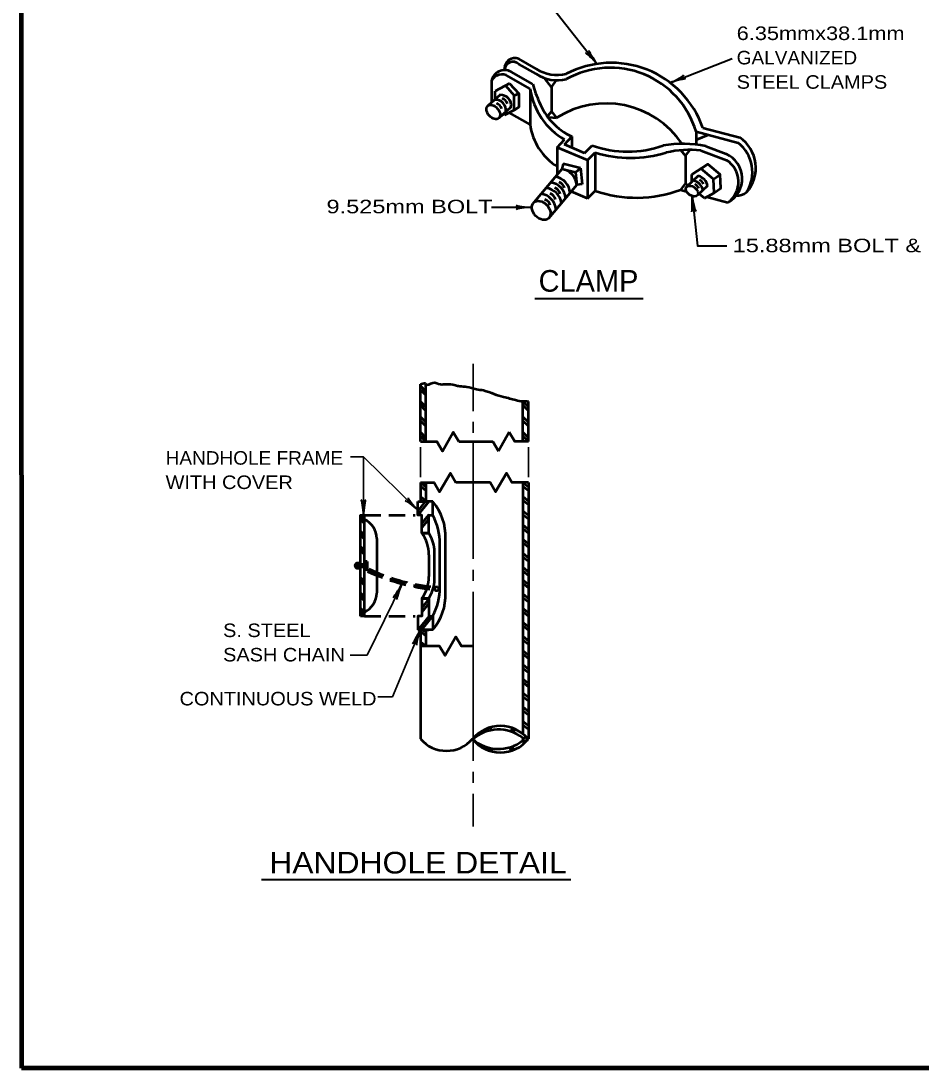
# Model space of a CAD drawing. Extents: x -23 to 690, y -228 to 443.
# Drawn here: x 24.3 to 190.5, y -0.6 to 192.8 of the extents above; entities that cross this region are included whole.
import ezdxf

# ---------------------------------------------------------------- set-up
doc = ezdxf.new("R2010")
doc.units = 0
doc.linetypes.add('MEDIUM_DASHED', pattern=[4.5, 3, -1.5])
doc.layers.add('1', color=7, linetype='Continuous', lineweight=35)

msp = doc.modelspace()

# ---------------------------------------------------------------- hatches: boundary and pattern name
at = {"layer": '1'}
msp.add_hatch(color=256, dxfattribs=at).paths.add_polyline_path([(87.083, 92.208, 1), (85.994, 92.208, 1)])

# ---------------------------------------------------------------- linework, layer by layer
at = {"layer": '1', "lineweight": 40}
for p, q in [((120.107, 198.311), (130.625, 184.906)), ((144.15, 181.442), (155.602, 185.881)), ((118.629, 158.401), (111.193, 158.401)), ((119.153, 141.59), (139.165, 141.59)), ((68.685, 34.21), (125.825, 34.21))]:
    msp.add_line(p, q, dxfattribs=at)
at = {"layer": '1', "lineweight": 53}
for p, q in [((119.441, 184.018), (116.221, 185.858)), ((119.441, 183.058), (116.221, 184.878)), ((118.301, 180.298), (114.281, 182.598)), ((118.801, 181.178), (114.781, 183.458)), ((122.241, 180.638), (120.961, 182.278)), ((122.241, 180.638), (123.201, 181.878)), ((111.181, 181.778), (111.181, 177.758)), ((114.521, 181.298), (111.841, 179.878)), ((113.761, 180.898), (115.381, 179.098)), ((118.301, 180.298), (118.301, 173.738)), ((112.741, 179.178), (110.481, 177.138)), ((111.841, 178.378), (111.841, 179.878)), ((114.761, 176.918), (112.521, 174.898)), ((122.241, 176.098), (123.181, 174.918)), ((113.361, 175.678), (113.561, 175.438)), ((118.301, 173.738), (114.501, 175.898)), ((121.761, 175.098), (123.181, 174.918)), ((148.961, 172.418), (156.741, 170.318)), ((148.961, 172.418), (148.961, 169.998)), ((150.181, 173.118), (157.001, 171.298)), ((123.321, 169.458), (124.681, 170.958)), ((124.641, 169.998), (126.001, 171.498)), ((126.001, 171.498), (126.001, 169.418)), ((149.081, 170.958), (151.161, 171.818)), ((128.901, 167.098), (123.321, 169.458)), ((123.321, 169.458), (123.321, 164.478)), ((128.361, 168.418), (124.641, 169.998)), ((128.361, 168.418), (129.781, 169.838)), ((128.901, 167.098), (130.321, 168.518)), ((130.321, 168.518), (130.321, 161.458)), ((147.001, 167.898), (146.161, 168.958)), ((147.001, 167.898), (147.881, 169.038)), ((149.841, 168.938), (154.561, 167.138)), ((150.721, 169.718), (154.501, 168.278)), ((124.401, 166.458), (124.161, 165.478)), ((127.581, 165.678), (124.401, 166.458)), ((128.901, 167.098), (128.901, 160.038)), ((147.001, 167.898), (147.001, 162.858)), ((124.161, 165.478), (118.981, 159.298)), ((126.661, 164.858), (124.161, 165.478)), ((127.581, 165.678), (126.661, 164.858)), ((126.661, 164.858), (126.921, 162.558)), ((127.581, 165.678), (127.921, 162.678)), ((148.181, 163.118), (148.141, 164.478)), ((152.181, 163.598), (149.861, 165.538)), ((126.921, 162.558), (121.721, 156.378)), ((127.921, 162.678), (126.921, 162.558)), ((147.001, 162.858), (146.061, 161.658)), ((147.001, 162.858), (147.381, 162.358)), ((149.361, 164.218), (147.141, 162.158)), ((128.901, 160.038), (125.881, 161.318)), ((128.901, 160.038), (130.321, 161.458)), ((146.061, 161.658), (147.161, 161.358)), ((151.081, 162.378), (149.241, 160.658)), ((150.481, 160.118), (149.521, 160.918)), ((150.941, 160.358), (154.821, 159.318)), ((98.073, 115.123), (98.073, 125.722)), ((99.073, 124.402), (98.073, 125.402)), ((99.073, 123.682), (98.073, 124.682)), ((99.073, 115.123), (99.073, 125.722)), ((99.073, 121.542), (98.073, 122.542)), ((116.973, 115.123), (116.973, 122.542)), ((117.973, 121.542), (116.973, 122.542)), ((117.973, 115.123), (117.973, 122.542)), ((99.073, 120.822), (98.073, 121.843)), ((117.973, 120.822), (116.973, 121.843)), ((99.073, 118.703), (98.073, 119.703)), ((99.073, 117.983), (98.073, 118.983)), ((117.973, 118.703), (116.973, 119.703)), ((117.973, 117.983), (116.973, 118.983)), ((99.073, 115.843), (98.073, 116.843)), ((99.073, 115.123), (98.073, 116.142)), ((114.453, 116.882), (112.433, 113.382)), ((117.973, 115.843), (116.973, 116.843)), ((117.973, 115.123), (116.973, 116.142)), ((105.133, 115.123), (111.433, 115.123)), ((112.433, 113.382), (111.433, 115.123)), ((98.073, 107.562), (98.073, 104.042)), ((98.073, 107.562), (99.073, 106.742)), ((98.073, 106.922), (99.073, 106.082)), ((99.073, 107.562), (99.073, 104.042)), ((116.973, 107.562), (117.973, 106.742)), ((116.973, 106.922), (117.973, 106.082)), ((117.973, 107.562), (117.973, 60.203)), ((98.073, 104.962), (99.073, 104.123)), ((116.973, 104.962), (117.973, 104.123)), ((97.573, 104.042), (99.573, 104.042)), ((99.573, 104.042), (97.573, 101.522)), ((98.933, 104.042), (97.573, 102.322)), ((98.073, 104.302), (98.393, 104.042)), ((100.333, 104.042), (98.313, 104.042)), ((116.973, 104.302), (117.973, 103.483)), ((87.733, 100.682), (86.973, 101.442)), ((87.733, 99.983), (86.973, 100.742)), ((87.733, 82.882), (87.733, 101.522)), ((99.573, 101.623), (98.313, 100.042)), ((99.573, 100.822), (98.313, 99.242)), ((116.973, 102.343), (117.973, 101.522)), ((116.973, 101.682), (117.973, 100.862)), ((116.973, 99.722), (117.973, 98.903)), ((116.973, 99.082), (117.973, 98.242)), ((87.733, 97.843), (86.973, 98.602)), ((87.733, 97.123), (86.973, 97.882)), ((90.013, 97.242), (90.013, 87.162)), ((99.573, 98.242), (98.313, 98.242)), ((102.653, 87.162), (102.653, 97.242)), ((116.973, 97.123), (117.973, 96.282)), ((87.733, 94.983), (86.973, 95.742)), ((87.733, 94.282), (86.973, 95.042)), ((100.633, 89.182), (100.633, 95.222)), ((101.653, 88.162), (101.653, 96.222)), ((116.973, 96.462), (117.973, 95.642)), ((88.233, 92.962), (87.733, 92.962)), ((87.853, 92.962), (87.853, 91.442)), ((87.933, 92.962), (87.933, 91.442)), ((87.933, 92.962), (87.933, 91.442)), ((88.013, 92.962), (88.013, 91.442)), ((88.013, 92.962), (88.013, 91.442)), ((88.073, 92.962), (88.073, 91.442)), ((88.133, 92.962), (88.133, 91.442)), ((88.153, 92.962), (88.153, 91.442)), ((88.193, 92.962), (88.193, 91.442)), ((88.233, 92.962), (88.233, 91.442)), ((99.633, 90.182), (99.633, 94.222)), ((116.973, 94.502), (117.973, 93.682)), ((116.973, 93.862), (117.973, 93.022)), ((87.733, 92.442), (86.973, 92.442)), ((87.733, 92.322), (86.973, 92.322)), ((87.733, 92.242), (86.973, 92.242)), ((87.733, 92.242), (86.973, 92.242)), ((87.733, 92.123), (86.973, 92.123)), ((87.733, 92.002), (86.973, 92.002)), ((87.733, 91.942), (86.973, 91.942)), ((88.233, 91.442), (87.733, 91.442)), ((116.973, 91.903), (117.973, 91.062)), ((116.973, 91.242), (117.973, 90.403)), ((87.733, 89.282), (86.973, 90.043)), ((87.733, 88.582), (86.973, 89.322)), ((116.973, 89.602), (117.973, 88.782)), ((87.733, 86.442), (86.973, 87.203)), ((116.973, 88.962), (117.973, 88.123)), ((87.733, 85.722), (86.973, 86.483)), ((99.573, 86.022), (98.313, 84.442)), ((99.573, 85.203), (98.313, 83.642)), ((116.973, 87.002), (117.973, 86.162)), ((116.973, 86.343), (117.973, 85.522)), ((87.733, 83.582), (86.973, 84.343)), ((87.733, 82.882), (86.973, 83.623)), ((116.973, 84.382), (117.973, 83.562)), ((116.973, 83.722), (117.973, 82.903)), ((87.733, 82.882), (86.973, 82.882)), ((99.653, 82.882), (97.633, 80.362)), ((100.333, 82.922), (98.273, 80.362)), ((116.973, 81.763), (117.973, 80.942)), ((97.573, 80.362), (99.573, 80.362)), ((98.073, 80.362), (98.073, 77.322)), ((98.073, 80.102), (99.073, 79.263)), ((100.333, 80.362), (98.313, 80.362)), ((98.553, 80.362), (99.073, 79.922)), ((99.073, 80.362), (99.073, 77.322)), ((116.973, 81.123), (117.973, 80.282)), ((98.073, 78.142), (99.053, 77.322)), ((98.073, 77.483), (98.253, 77.322)), ((116.973, 79.162), (117.973, 78.322)), ((116.973, 78.502), (117.973, 77.682)), ((116.973, 76.543), (117.973, 75.722)), ((116.973, 75.903), (117.973, 75.062)), ((116.973, 73.942), (117.973, 73.102)), ((116.973, 73.282), (117.973, 72.442)), ((116.973, 71.322), (117.973, 70.483)), ((116.973, 70.662), (117.973, 69.843)), ((116.973, 68.703), (117.973, 67.882)), ((116.973, 68.062), (117.973, 67.222)), ((116.973, 66.102), (117.973, 65.263)), ((116.973, 65.442), (117.973, 64.623)), ((110.433, 62.142), (110.633, 61.703)), ((110.913, 62.302), (111.133, 61.802)), ((115.013, 62.203), (114.713, 61.562)), ((115.473, 62.023), (115.193, 61.383)), ((116.973, 63.482), (117.973, 62.663)), ((116.973, 62.822), (117.973, 62.002)), ((116.673, 59.722), (117.853, 60.042)), ((116.973, 60.322), (117.613, 60.502)), ((110.613, 58.062), (110.833, 58.523)), ((111.093, 57.922), (111.333, 58.442)), ((114.833, 58.002), (114.533, 58.663)), ((115.313, 58.182), (115.013, 58.822))]:
    msp.add_line(p, q, dxfattribs=at)
at = {"layer": '1'}
for p, q in [((107.773, 120.763), (107.773, 129.502)), ((107.773, 118.763), (107.773, 116.742)), ((107.773, 115.123), (107.773, 111.362)), ((107.773, 114.722), (107.773, 93.462)), ((87.519, 112.294), (85.131, 112.307)), ((98.073, 108.582), (98.073, 114.123)), ((117.973, 108.582), (117.973, 114.123)), ((107.773, 91.442), (107.773, 89.422)), ((107.773, 87.403), (107.773, 56.122)), ((107.773, 54.102), (107.773, 52.082)), ((107.773, 50.082), (107.773, 44.042))]:
    msp.add_line(p, q, dxfattribs=at)
at = {"layer": '1', "linetype": 'MEDIUM_DASHED', "lineweight": 53}
for p, q in [((87.733, 101.522), (97.053, 101.522)), ((87.733, 82.882), (97.053, 82.882))]:
    msp.add_line(p, q, dxfattribs=at)
at = {"layer": '1', "lineweight": 158}
msp.add_line((684.026, -0.611), (24.36, -0.611), dxfattribs=at)
msp.add_lwpolyline([(684.026, 437.805), (24.276, 437.722), (24.36, -0.611)], dxfattribs=at)
at = {"layer": '1', "lineweight": 53}
for points in [[(114.521, 181.298), (116.201, 179.438), (116.201, 176.918), (115.381, 176.338), (113.561, 175.438)], [(122.241, 180.638), (122.241, 176.098), (121.601, 175.298)], [(115.381, 176.338), (115.381, 179.098), (116.201, 179.438)], [(150.481, 160.118), (152.261, 161.078), (153.501, 161.938), (153.421, 164.458), (151.101, 166.398), (148.141, 164.478)], [(152.261, 161.078), (152.181, 163.598), (153.421, 164.458)], [(98.073, 115.123), (101.093, 115.123), (102.093, 113.382), (104.113, 116.882), (105.133, 115.123)], [(117.973, 115.123), (115.453, 115.123), (114.453, 116.882)], [(98.073, 107.562), (100.593, 107.562), (101.593, 105.822), (103.613, 109.322), (104.613, 107.562)], [(117.973, 107.562), (114.953, 107.562), (113.953, 109.322), (111.933, 105.822), (110.913, 107.562), (104.613, 107.562)], [(116.973, 107.562), (116.973, 87.123), (116.973, 61.102)], [(98.313, 98.242), (98.313, 101.522), (97.573, 101.522), (97.573, 104.042)], [(98.313, 98.242), (99.573, 98.242), (99.573, 101.522), (100.333, 101.522), (100.333, 104.042)], [(86.973, 82.882), (86.973, 101.522), (87.733, 101.522)], [(99.573, 86.142), (98.313, 86.142), (98.313, 82.882), (97.573, 82.882), (97.573, 80.362)], [(98.313, 86.142), (99.573, 86.142), (99.573, 82.882), (100.333, 82.882), (100.333, 80.362)], [(107.653, 77.322), (105.633, 77.322), (104.613, 79.082), (102.613, 75.582), (101.593, 77.322), (98.073, 77.322), (98.073, 60.203)]]:
    msp.add_lwpolyline(points, dxfattribs=at)
at = {"layer": '1', "lineweight": 40}
msp.add_lwpolyline([(148.224, 160.489), (149.21, 151.327), (154.65, 151.327)], dxfattribs=at)
at = {"layer": '1'}
for points in [[(97.573, 102.459), (87.519, 112.294), (87.519, 101.522)], [(94.602, 88.752), (88.2, 75.673), (85.088, 75.679)], [(98.034, 80.345), (92.887, 67.957), (90.194, 67.957)]]:
    msp.add_lwpolyline(points, dxfattribs=at)
at = {"layer": '1', "lineweight": 53}
for centre, radius in [((86.538, 92.208), 0.545), ((101.059, 87.924), 0.378)]:
    msp.add_circle(centre, radius, dxfattribs=at)
for centre, radius, start, end in [((115.524, 184.021), 1.967, 68.98454, 184.96528), ((115.167, 183.674), 1.613, 48.79801, 173.73367), ((123.336, 189.995), 7.131, 236.83956, 283.32479), ((133.299, 167.215), 17.892, 19.29143, 117.70819), ((133.089, 167.641), 16.566, 16.7434, 119.30902), ((113.595, 181.305), 2.464, 61.16852, 169.07366), ((113.089, 180.813), 2.14, 56.06469, 153.37669), ((123.284, 188.727), 6.854, 235.84201, 284.32234), ((130.95, 182.087), 12.777, 188.06983, 240.59731), ((139.874, 186.899), 21.84, 195.21089, 204.37149), ((111.911, 176.397), 1.909, 349.61263, 94.38617), ((112.883, 177.267), 1.909, 349.61263, 94.38617), ((112.506, 176.938), 1.742, 20.88408, 69.09679), ((111.455, 176.011), 1.742, 20.88408, 69.09679), ((131.129, 182.346), 12.008, 201.80286, 244.70416), ((132.334, 160.727), 16.89, 33.86522, 122.8499), ((129.015, 175.115), 10.803, 187.30417, 238.23787), ((152.415, 164.901), 6.939, 327.83586, 51.43283), ((153.241, 165.692), 6.752, 318.38164, 56.15447), ((136.339, 188.098), 19.396, 250.25742, 289.74258), ((136.873, 190.32), 22.763, 253.27137, 286.72862), ((146.475, 148.391), 21.748, 78.72641, 99.48511), ((147.907, 149.265), 19.77, 84.35687, 103.10294), ((152.516, 163.715), 4.969, 297.71146, 66.56345), ((152.083, 163.134), 4.701, 305.70046, 58.26699), ((123.731, 162.304), 3.193, 4.65558, 82.27962), ((121.684, 159.86), 3.193, 4.74535, 82.35434), ((122.509, 160.869), 3.193, 4.32722, 81.54855), ((123.164, 161.617), 1.531, 14.18506, 70.66849), ((147.854, 161.069), 2.406, 11.41742, 74.57891), ((148.099, 161.38), 1.432, 21.50211, 64.13038), ((148.72, 161.894), 2.406, 11.41742, 74.57891), ((148.974, 162.181), 1.432, 21.50211, 64.13038), ((119.913, 157.722), 3.193, 5.19441, 82.73082), ((120.921, 158.791), 3.193, 7.29827, 83.92311), ((121.515, 159.509), 1.531, 14.18506, 70.66849), ((122.37, 160.548), 1.531, 14.18506, 70.66849), ((137.914, 183.47), 23.278, 250.96338, 290.4942), ((156.114, 164.254), 3.743, 273.11257, 305.52158), ((120.537, 158.409), 1.531, 14.18506, 70.66849), ((92.937, 97.724), 9.729, 357.13004, 40.48815), ((85.9, 97.092), 4.106, 2.02606, 63.44439), ((89.84, 96.116), 11.806, 0.54939, 27.24732), ((92.647, 94.174), 6.982, 0.31998, 35.66459), ((93.502, 94.423), 7.18, 6.38376, 32.16514), ((92.647, 90.22), 6.982, 324.33541, 359.68002), ((93.502, 89.972), 7.18, 327.83486, 353.61624), ((85.9, 87.302), 4.106, 296.55561, 357.97394), ((89.84, 88.314), 11.806, 332.75268, 359.45061), ((92.937, 86.705), 9.729, 319.51185, 2.86996), ((112.451, 54.751), 7.178, 51.54154, 132.04732), ((112.81, 56.013), 6.576, 38.8447, 141.1553), ((102.856, 64.313), 6.317, 220.71167, 319.28832), ((112.81, 64.262), 6.576, 218.22248, 321.77751), ((112.451, 65.523), 7.178, 227.95268, 308.4983), ((116.738, 60.139), 0.294, 307.8273, 52.77092)]:
    msp.add_arc(centre, radius, start, end, dxfattribs=at)
at = {"layer": '1', "linetype": 'MEDIUM_DASHED', "lineweight": 53}
for centre, radius, start, end in [((104.93, 127.366), 39.613, 245.08086, 263.60629), ((104.414, 125.821), 38.237, 245.04728, 263.19799), ((104.079, 124.62), 36.501, 244.77769, 263.49597)]:
    msp.add_arc(centre, radius, start, end, dxfattribs=at)
at = {"layer": '1', "lineweight": 40}
for centre, major_axis, ratio, start_param, end_param in [((129.734, 185.594), (1.225, -1.308), 0.122415, 0.8963533, 3.1415927), ((130.1, 185.919), (-0.946, 1.49), 0.07063, 6.2823074, 8.5597026), ((145.067, 182.094), (-1.609, -0.791), 0.122415, 0.8963533, 3.1415927), ((145.067, 182.094), (-1.609, -0.791), 0.122415, 0.8963533, 3.1415927), ((145.271, 181.65), (-1.701, -0.471), 0.07063, 3.1407148, 5.41811), ((145.271, 181.65), (-1.701, -0.471), 0.07063, 3.1407148, 5.41811), ((117.508, 158.612), (1.756, -0.176), 0.07063, 3.1407148, 5.41811), ((117.508, 158.612), (1.756, -0.176), 0.07063, 3.1407148, 5.41811), ((148.133, 159.352), (-0.013, 1.765), 0.07063, 3.1407148, 5.41811), ((148.133, 159.352), (-0.013, 1.765), 0.07063, 3.1407148, 5.41811), ((148.615, 159.433), (-0.346, 1.759), 0.122415, 0.8963533, 3.1415927), ((148.615, 159.433), (-0.346, 1.759), 0.122415, 0.8963533, 3.1415927), ((117.538, 158.125), (1.786, 0.156), 0.122415, 0.8963533, 3.1415927), ((117.538, 158.125), (1.786, 0.156), 0.122415, 0.8963533, 3.1415927), ((96.92, 103.394), (-1.133, 1.354), 0.07063, 6.2823074, 8.5597026), ((96.92, 103.394), (-1.133, 1.354), 0.07063, 6.2823074, 8.5597026), ((87.243, 102.614), (0.156, -1.786), 0.122415, 0.8963533, 3.1415927), ((87.731, 102.643), (0.176, 1.756), 0.07063, 6.2823074, 8.5597026), ((96.6, 103.024), (1.386, -1.137), 0.122415, 0.8963533, 3.1415927), ((96.6, 103.024), (1.386, -1.137), 0.122415, 0.8963533, 3.1415927), ((93.92, 87.839), (0.93, 1.5), 0.07063, 3.1407148, 5.41811), ((94.371, 87.65), (0.645, 1.672), 0.122415, 0.8963533, 3.1415927), ((97.408, 79.391), (0.836, 1.555), 0.07063, 3.1407148, 5.41811), ((97.87, 79.231), (0.541, 1.709), 0.122415, 0.8963533, 3.1415927)]:
    msp.add_ellipse(centre, major_axis=major_axis, ratio=ratio, start_param=start_param, end_param=end_param, dxfattribs=at)
at = {"layer": '1', "lineweight": 53}
for centre, major_axis, ratio in [((111.501, 176.024), (1.012, -1.124), 0.663346), ((148.192, 161.402), (1.044, -0.75), 0.624582), ((120.353, 157.839), (1.377, -1.452), 0.71432)]:
    msp.add_ellipse(centre, major_axis=major_axis, ratio=ratio, dxfattribs=at)
for points in [[(98.073, 125.722), (98.493, 125.862), (98.933, 125.922), (99.073, 125.722), (100.353, 126.002), (101.733, 125.722), (102.733, 125.763), (104.493, 125.562), (105.293, 125.382), (106.613, 125.263), (108.373, 124.822), (109.713, 124.602), (111.613, 123.942), (113.393, 123.422), (115.613, 122.822), (116.973, 122.542)], [(116.593, 122.623), (117.453, 122.602), (117.973, 122.542)]]:
    msp.add_spline(points, degree=3, dxfattribs=at)

# ---------------------------------------------------------------- texts
at = {"layer": '1'}
for s, height, width, p in [('6.35mmx38.1mm', 2.5, 1.2, (156.453, 189.32)), ('GALVANIZED', 2.5, 1.05, (156.453, 184.82)), ('STEEL CLAMPS', 2.5, 1.1, (156.453, 180.32)), ('9.525mm BOLT', 2.5, 1.3, (80.704, 157.307)), ('15.88mm BOLT & HEX NUT', 2.5, 1.3, (155.71, 150.116)), ('HANDHOLE FRAME', 2.5, 1.05, (50.995, 110.868)), ('WITH COVER', 2.5, 1.1, (50.995, 106.368)), ('S. STEEL', 2.5, 1.1, (61.609, 79.011)), ('SASH CHAIN', 2.5, 1.1, (61.609, 74.511)), ('CONTINUOUS WELD', 2.5, 1.1, (53.568, 66.388)), ('HANDHOLE DETAIL', 4, 1.1, (70.132, 35.336))]:
    msp.add_text(s, height=height, dxfattribs=dict(at, width=width)).set_placement(p)
msp.add_text('CLAMP', height=4, dxfattribs=at).set_placement((119.872, 142.823))

doc.saveas('drawing.dxf')
